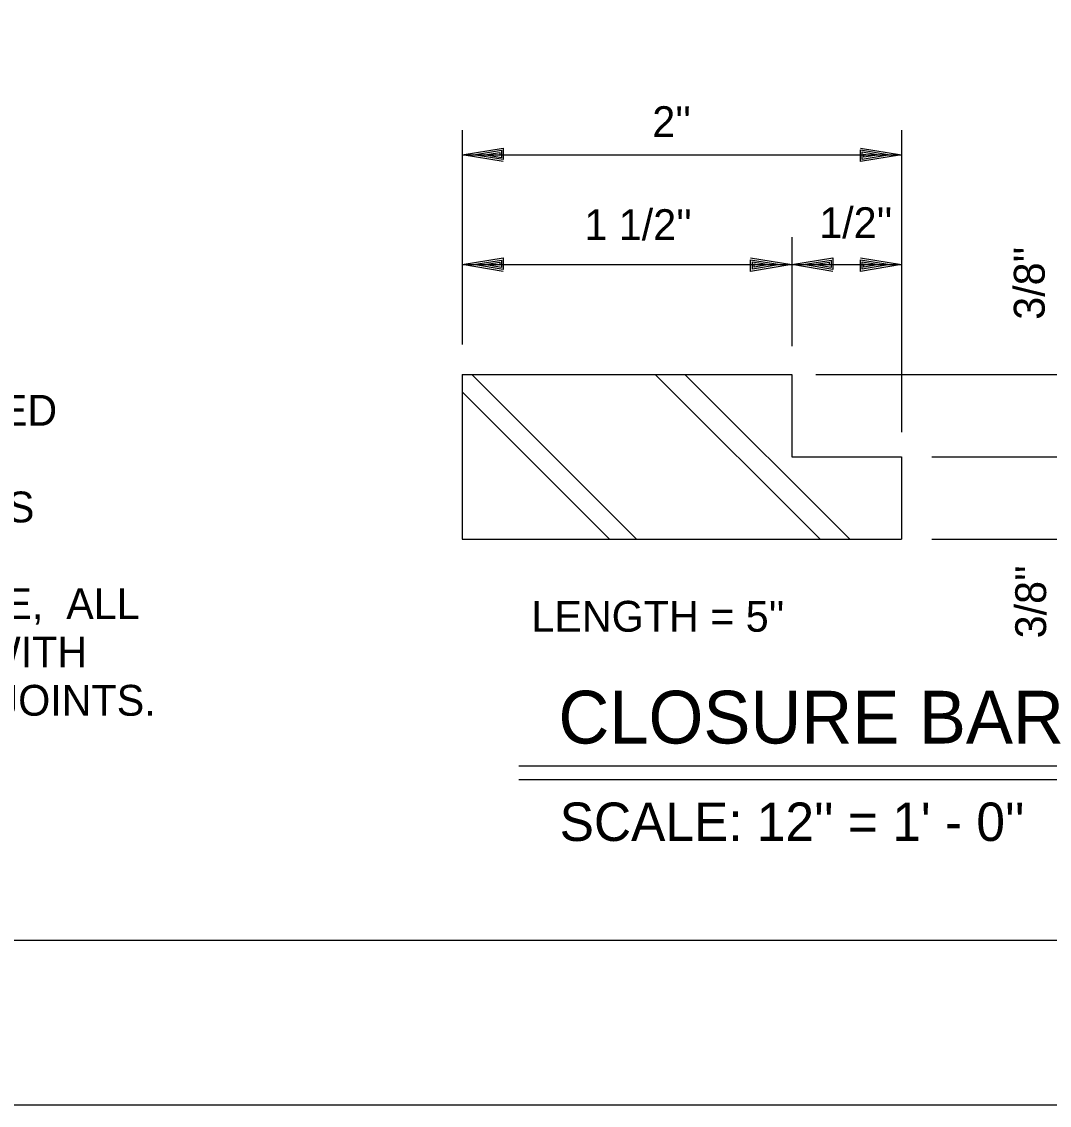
# Model space of a CAD drawing. Extents: x 22371.58 to 22374.41, y 22370.57 to 22372.4.
# Drawn here: x 22372.3521 to 22372.7418, y 22370.5694 to 22370.9805 of the extents above; entities that cross this region are included whole.
import ezdxf

# ---------------------------------------------------------------- set-up
doc = ezdxf.new("R2010")
doc.units = 0
for name, color, linetype in [('G-ANNO-SYMB', 7, 'Continuous'), ('G-ANNO-TTBL', 7, 'Continuous'), ('S-ANNO-DIMS', 7, 'Continuous'), ('S-ANNO-NOTE', 7, 'Continuous'), ('S-ANNO-TEXT', 7, 'Continuous'), ('S-GATE-SEAL', 7, 'Continuous')]:
    doc.layers.add(name, color=color, linetype=linetype)

msp = doc.modelspace()

# ---------------------------------------------------------------- linework, layer by layer
at = {"layer": 'G-ANNO-SYMB'}
msp.add_lwpolyline([(22371.57831, 22372.40278), (22374.41164, 22372.40278), (22374.41164, 22370.56945), (22371.57831, 22370.56945)], close=True, dxfattribs=at)
at = {"layer": 'G-ANNO-TTBL'}
msp.add_lwpolyline([(22371.77622, 22372.34028), (22374.19289, 22372.34028), (22374.19289, 22370.63195), (22371.77622, 22370.63195)], close=True, dxfattribs=at)
msp.add_lwpolyline([(22371.77622, 22372.34028), (22374.19289, 22372.34028), (22374.19289, 22370.63195), (22371.77622, 22370.63195)], close=True, dxfattribs=at)
at = {"layer": 'S-ANNO-DIMS'}
for p, q in [((22372.51912, 22370.93935), (22372.51912, 22370.85803)), ((22372.68579, 22370.93932), (22372.68579, 22370.82485)), ((22372.51912, 22370.92999), (22372.68579, 22370.92999)), ((22372.51912, 22370.92999), (22372.51912, 22370.92999)), ((22372.52346, 22370.92999), (22372.52346, 22370.92999)), ((22372.68146, 22370.92999), (22372.68146, 22370.92999)), ((22372.68579, 22370.92999), (22372.68579, 22370.92999)), ((22372.64412, 22370.89874), (22372.64412, 22370.85736)), ((22372.51912, 22370.88833), (22372.64412, 22370.88833)), ((22372.51912, 22370.88833), (22372.51912, 22370.88833)), ((22372.52346, 22370.88833), (22372.52346, 22370.88833)), ((22372.63979, 22370.88833), (22372.63979, 22370.88833)), ((22372.64412, 22370.88833), (22372.68579, 22370.88833)), ((22372.64412, 22370.88833), (22372.64412, 22370.88833)), ((22372.64412, 22370.88833), (22372.64412, 22370.88833)), ((22372.64846, 22370.88833), (22372.64846, 22370.88833)), ((22372.68146, 22370.88833), (22372.68146, 22370.88833)), ((22372.68579, 22370.88833), (22372.68579, 22370.88833)), ((22372.58529, 22370.78416), (22372.52279, 22370.84666)), ((22372.65487, 22370.78416), (22372.59237, 22370.84666)), ((22372.66612, 22370.78416), (22372.60362, 22370.84666)), ((22372.65332, 22370.84666), (22372.80091, 22370.84666)), ((22372.57504, 22370.78416), (22372.51912, 22370.84008)), ((22372.69733, 22370.81541), (22372.76085, 22370.81541)), ((22372.69733, 22370.78416), (22372.80091, 22370.78416))]:
    msp.add_line(p, q, dxfattribs=at)
for points in [[(22372.53471, 22370.92741), (22372.51912, 22370.92999), (22372.53471, 22370.93258), (22372.53471, 22370.92816), (22372.52346, 22370.92999), (22372.53404, 22370.93174), (22372.53404, 22370.92891), (22372.52762, 22370.92999), (22372.53337, 22370.93091), (22372.53337, 22370.92974), (22372.53196, 22370.92999)], [(22372.67021, 22370.93258), (22372.68579, 22370.92999), (22372.67021, 22370.92741), (22372.67021, 22370.93183), (22372.68146, 22370.92999), (22372.67087, 22370.92824), (22372.67087, 22370.93108), (22372.67729, 22370.92999), (22372.67154, 22370.92908), (22372.67154, 22370.93024), (22372.67296, 22370.92999)], [(22372.53471, 22370.88574), (22372.51912, 22370.88833), (22372.53471, 22370.89091), (22372.53471, 22370.88649), (22372.52346, 22370.88833), (22372.53404, 22370.89008), (22372.53404, 22370.88724), (22372.52762, 22370.88833), (22372.53337, 22370.88924), (22372.53337, 22370.88808), (22372.53196, 22370.88833)], [(22372.62854, 22370.89091), (22372.64412, 22370.88833), (22372.62854, 22370.88574), (22372.62854, 22370.89016), (22372.63979, 22370.88833), (22372.62921, 22370.88658), (22372.62921, 22370.88941), (22372.63562, 22370.88833), (22372.62987, 22370.88741), (22372.62987, 22370.88858), (22372.63129, 22370.88833)], [(22372.65971, 22370.88574), (22372.64412, 22370.88833), (22372.65971, 22370.89091), (22372.65971, 22370.88649), (22372.64846, 22370.88833), (22372.65904, 22370.89008), (22372.65904, 22370.88724), (22372.65262, 22370.88833), (22372.65837, 22370.88924), (22372.65837, 22370.88808), (22372.65696, 22370.88833)], [(22372.67021, 22370.89091), (22372.68579, 22370.88833), (22372.67021, 22370.88574), (22372.67021, 22370.89016), (22372.68146, 22370.88833), (22372.67087, 22370.88658), (22372.67087, 22370.88941), (22372.67729, 22370.88833), (22372.67154, 22370.88741), (22372.67154, 22370.88858), (22372.67296, 22370.88833)]]:
    msp.add_lwpolyline(points, dxfattribs=at)
at = {"layer": 'S-ANNO-TEXT'}
for p, q in [((22372.5406, 22370.69822), (22372.7832, 22370.69822)), ((22372.5406, 22370.69301), (22372.78424, 22370.69301))]:
    msp.add_line(p, q, dxfattribs=at)
at = {"layer": 'S-GATE-SEAL'}
for p, q in [((22372.51912, 22370.84666), (22372.51912, 22370.78416)), ((22372.51912, 22370.84666), (22372.64412, 22370.84666)), ((22372.64412, 22370.84666), (22372.64412, 22370.81541)), ((22372.64412, 22370.81541), (22372.68579, 22370.81541)), ((22372.68579, 22370.81541), (22372.68579, 22370.78416)), ((22372.51912, 22370.78416), (22372.68579, 22370.78416))]:
    msp.add_line(p, q, dxfattribs=at)

# ---------------------------------------------------------------- texts
at = {"layer": 'S-ANNO-DIMS'}
for s, height, p in [("2''", 0.011698, (22372.59125, 22370.93672)), ("1 1/2''", 0.011698, (22372.56551, 22370.89765)), ("1/2''", 0.011698, (22372.65458, 22370.8984)), ("LENGTH = 5''", 0.0116979, (22372.54542, 22370.7491))]:
    msp.add_text(s, height=height, dxfattribs=at).set_placement(p)
for p in [(22372.74007, 22370.86743), (22372.74061, 22370.74659)]:
    msp.add_text("3/8''", height=0.011698, rotation=90, dxfattribs=at).set_placement(p)
at = {"layer": 'S-ANNO-NOTE'}
for s, p in [('LEAST 50% OF THE MINIMUM TENSILE STRENGTH REQUIRED', (22371.89705, 22370.82723)), ('SEAL CLAMP ANGLES SHALL BE PAINTED ON ALL SIDES', (22371.9283, 22370.79056)), ('AFTER ASSEMBLY AND SEAL ADJUSTMENTS ARE MADE,  ALL', (22371.9283, 22370.75389)), ('GAPS IN SEALS AND SEAL SUPPORTS SHALL BE SEALED WITH', (22371.89705, 22370.73556)), ('A SILICONE RUBBER SEALANT TO PROVIDE WATERTIGHT JOINTS.', (22371.89705, 22370.71723))]:
    msp.add_text(s, height=0.0116979, dxfattribs=at).set_placement(p)
at = {"layer": 'S-ANNO-TEXT'}
msp.add_text('CLOSURE BAR', height=0.02, dxfattribs=at).set_placement((22372.55564, 22370.70669))
at = {"layer": 'S-GATE-SEAL'}
msp.add_text("SCALE: 12'' = 1' - 0''", height=0.0145829, dxfattribs=at).set_placement((22372.55612, 22370.66972))

doc.saveas('drawing.dxf')
